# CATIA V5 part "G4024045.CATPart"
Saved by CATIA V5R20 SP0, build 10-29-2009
Part number: G4024045
Revision: 4
Definition: design
Nomenclature: G4024045
Source: made
Description: NOT SPECIFIED
Bounding box of the stored display mesh (mm): x -25 to 45, y -28 to 28, z -28 to 28
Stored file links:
  C:\Users\Raffaele\Desktop\3D X SITO CF\BOLEX\26-BUSH REF 402\G4024045.CATPart
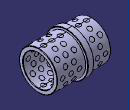
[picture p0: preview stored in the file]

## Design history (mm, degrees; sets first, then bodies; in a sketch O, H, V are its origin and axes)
Body1 "MANIFOLD_SOLID_BREP #10309" (main body)
  Solid1: solid without history
Body2 "MANIFOLD_SOLID_BREP #10468"
  Solid2: solid without history
Body3 "MANIFOLD_SOLID_BREP #10627"
  Solid3: solid without history
Body4 "MANIFOLD_SOLID_BREP #10784"
  Solid4: solid without history
Body5 "MANIFOLD_SOLID_BREP #10945"
  Solid5: solid without history
Body6 "MANIFOLD_SOLID_BREP #11102"
  Solid6: solid without history
Body7 "MANIFOLD_SOLID_BREP #11259"
  Solid7: solid without history
Body8 "MANIFOLD_SOLID_BREP #11420"
  Solid8: solid without history
Body9 "MANIFOLD_SOLID_BREP #11577"
  Solid9: solid without history
Body10 "MANIFOLD_SOLID_BREP #11738"
  Solid10: solid without history
Body11 "MANIFOLD_SOLID_BREP #11899"
  Solid11: solid without history
Body12 "MANIFOLD_SOLID_BREP #12060"
  Solid12: solid without history
Body13 "MANIFOLD_SOLID_BREP #12221"
  Solid13: solid without history
Body14 "MANIFOLD_SOLID_BREP #12382"
  Solid14: solid without history
Body15 "MANIFOLD_SOLID_BREP #12543"
  Solid15: solid without history
Body16 "MANIFOLD_SOLID_BREP #12704"
  Solid16: solid without history
Body17 "MANIFOLD_SOLID_BREP #12865"
  Solid17: solid without history
Body18 "MANIFOLD_SOLID_BREP #13022"
  Solid18: solid without history
Body19 "MANIFOLD_SOLID_BREP #13183"
  Solid19: solid without history
Body20 "MANIFOLD_SOLID_BREP #13340"
  Solid20: solid without history
Body21 "MANIFOLD_SOLID_BREP #13497"
  Solid21: solid without history
Body22 "MANIFOLD_SOLID_BREP #13658"
  Solid22: solid without history
Body23 "MANIFOLD_SOLID_BREP #13815"
  Solid23: solid without history
Body24 "MANIFOLD_SOLID_BREP #13974"
  Solid24: solid without history
Body25 "MANIFOLD_SOLID_BREP #14133"
  Solid25: solid without history
Body26 "MANIFOLD_SOLID_BREP #14290"
  Solid26: solid without history
Body27 "MANIFOLD_SOLID_BREP #14451"
  Solid27: solid without history
Body28 "MANIFOLD_SOLID_BREP #14608"
  Solid28: solid without history
Body29 "MANIFOLD_SOLID_BREP #14765"
  Solid29: solid without history
Body30 "MANIFOLD_SOLID_BREP #14926"
  Solid30: solid without history
Body31 "MANIFOLD_SOLID_BREP #15083"
  Solid31: solid without history
Body32 "MANIFOLD_SOLID_BREP #15242"
  Solid32: solid without history
Body33 "MANIFOLD_SOLID_BREP #15401"
  Solid33: solid without history
Body34 "MANIFOLD_SOLID_BREP #15562"
  Solid34: solid without history
Body35 "MANIFOLD_SOLID_BREP #15723"
  Solid35: solid without history
Body36 "MANIFOLD_SOLID_BREP #15884"
  Solid36: solid without history
Body37 "MANIFOLD_SOLID_BREP #16045"
  Solid37: solid without history
Body38 "MANIFOLD_SOLID_BREP #16206"
  Solid38: solid without history
Body39 "MANIFOLD_SOLID_BREP #16367"
  Solid39: solid without history
Body40 "MANIFOLD_SOLID_BREP #16528"
  Solid40: solid without history
Body41 "MANIFOLD_SOLID_BREP #16689"
  Solid41: solid without history
Body42 "MANIFOLD_SOLID_BREP #16846"
  Solid42: solid without history
Body43 "MANIFOLD_SOLID_BREP #17003"
  Solid43: solid without history
Body44 "MANIFOLD_SOLID_BREP #17164"
  Solid44: solid without history
Body45 "MANIFOLD_SOLID_BREP #17325"
  Solid45: solid without history
Body46 "MANIFOLD_SOLID_BREP #17482"
  Solid46: solid without history
Body47 "MANIFOLD_SOLID_BREP #17639"
  Solid47: solid without history
Body48 "MANIFOLD_SOLID_BREP #17796"
  Solid48: solid without history
Body49 "MANIFOLD_SOLID_BREP #17953"
  Solid49: solid without history
Body50 "MANIFOLD_SOLID_BREP #18114"
  Solid50: solid without history
Body51 "MANIFOLD_SOLID_BREP #18275"
  Solid51: solid without history
Body52 "MANIFOLD_SOLID_BREP #18432"
  Solid52: solid without history
Body53 "MANIFOLD_SOLID_BREP #18589"
  Solid53: solid without history
Body54 "MANIFOLD_SOLID_BREP #18748"
  Solid54: solid without history
Body55 "MANIFOLD_SOLID_BREP #18907"
  Solid55: solid without history
Body56 "MANIFOLD_SOLID_BREP #19066"
  Solid56: solid without history
Body57 "MANIFOLD_SOLID_BREP #19225"
  Solid57: solid without history
Body58 "MANIFOLD_SOLID_BREP #19386"
  Solid58: solid without history
Body59 "MANIFOLD_SOLID_BREP #19547"
  Solid59: solid without history
Body60 "MANIFOLD_SOLID_BREP #19708"
  Solid60: solid without history
Body61 "MANIFOLD_SOLID_BREP #19869"
  Solid61: solid without history
Body62 "MANIFOLD_SOLID_BREP #20030"
  Solid62: solid without history
Body63 "MANIFOLD_SOLID_BREP #20191"
  Solid63: solid without history
Body64 "MANIFOLD_SOLID_BREP #20352"
  Solid64: solid without history
Body65 "MANIFOLD_SOLID_BREP #20513"
  Solid65: solid without history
